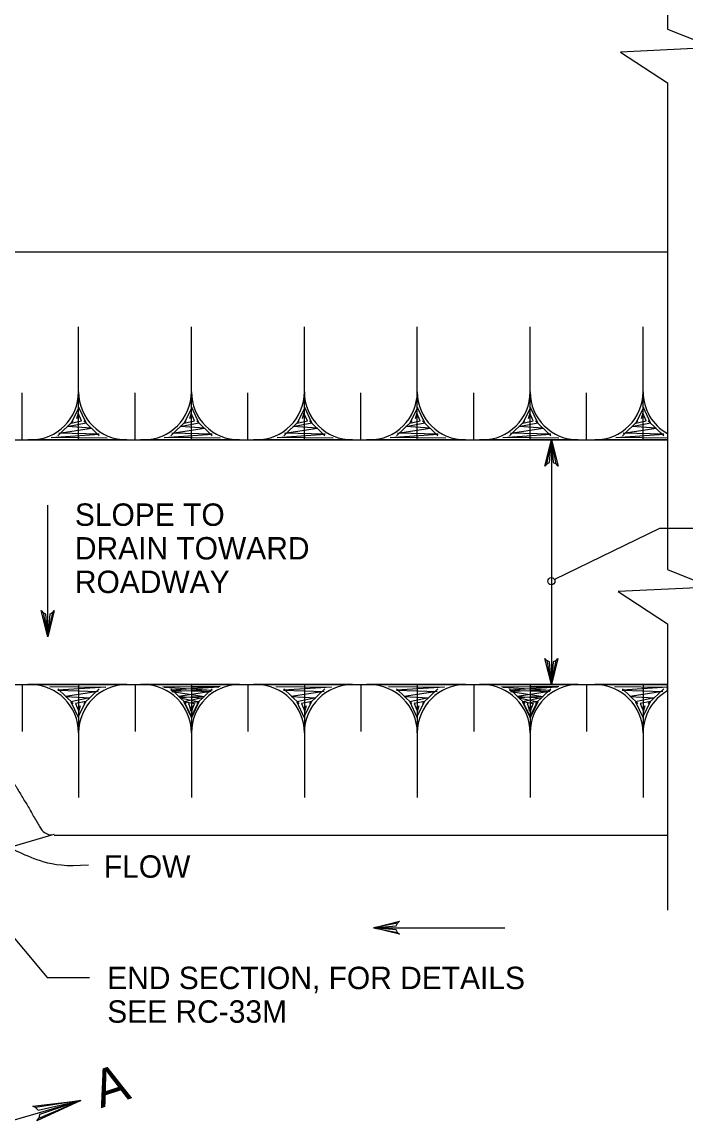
# Model space of a CAD drawing. Extents: x 636462 to 637367, y 299944 to 300538.
# Drawn here: x 636754.8 to 636843.6, y 300281.9 to 300429.2 of the extents above; entities that cross this region are included whole.
import ezdxf

# ---------------------------------------------------------------- set-up
doc = ezdxf.new("R2010")
doc.units = 0
doc.layers.add('Default', color=7, linetype='Continuous')

msp = doc.modelspace()

# ---------------------------------------------------------------- linework, layer by layer
at = {"layer": 'Default'}
for p, q in [((636841.16, 300465.99), (636841.16, 300428.23)), ((636841.16, 300421.06), (636841.16, 300355.93)), ((636726.65, 300398.45), (636841.16, 300398.45)), ((636762.35, 300373.27), (636762.35, 300388.38)), ((636777.45, 300373.27), (636777.45, 300388.38)), ((636792.56, 300373.27), (636792.56, 300388.38)), ((636807.67, 300373.27), (636807.67, 300388.38)), ((636822.78, 300373.27), (636822.78, 300388.38)), ((636837.89, 300373.27), (636837.89, 300388.38)), ((636754.79, 300373.27), (636754.79, 300379.56)), ((636769.9, 300373.27), (636769.9, 300379.56)), ((636785.01, 300373.27), (636785.01, 300379.56)), ((636800.12, 300373.27), (636800.12, 300379.56)), ((636815.23, 300373.27), (636815.23, 300379.56)), ((636830.33, 300373.27), (636830.33, 300379.56)), ((636759.59, 300373.83), (636761.64, 300375.82)), ((636765.1, 300373.83), (636763.05, 300375.82)), ((636765.1, 300373.83), (636763.05, 300375.82)), ((636765.1, 300373.83), (636763.05, 300375.82)), ((636774.7, 300373.83), (636776.75, 300375.82)), ((636780.21, 300373.83), (636778.16, 300375.82)), ((636780.21, 300373.83), (636778.16, 300375.82)), ((636780.21, 300373.83), (636778.16, 300375.82)), ((636789.81, 300373.83), (636791.86, 300375.82)), ((636795.32, 300373.83), (636793.27, 300375.82)), ((636795.32, 300373.83), (636793.27, 300375.82)), ((636795.32, 300373.83), (636793.27, 300375.82)), ((636804.91, 300373.83), (636806.97, 300375.82)), ((636810.43, 300373.83), (636808.38, 300375.82)), ((636810.43, 300373.83), (636808.38, 300375.82)), ((636810.43, 300373.83), (636808.38, 300375.82)), ((636820.02, 300373.83), (636822.07, 300375.82)), ((636825.54, 300373.83), (636823.49, 300375.82)), ((636825.54, 300373.83), (636823.49, 300375.82)), ((636825.54, 300373.83), (636823.49, 300375.82)), ((636835.13, 300373.83), (636837.18, 300375.82)), ((636840.65, 300373.83), (636838.59, 300375.82)), ((636733.01, 300373.27), (636841.16, 300373.27)), ((636768.79, 300373.27), (636755.54, 300373.27)), ((636755.54, 300373.27), (636755.9, 300373.27)), ((636783.89, 300373.27), (636770.65, 300373.27)), ((636770.65, 300373.27), (636771.01, 300373.27)), ((636799, 300373.27), (636785.76, 300373.27)), ((636785.76, 300373.27), (636786.12, 300373.27)), ((636814.11, 300373.27), (636800.87, 300373.27)), ((636800.87, 300373.27), (636801.23, 300373.27)), ((636810.61, 300373.27), (636822.17, 300373.27)), ((636829.22, 300373.27), (636815.98, 300373.27)), ((636815.98, 300373.27), (636816.34, 300373.27)), ((636825.62, 300373.27), (636825.62, 300340.53)), ((636841.16, 300373.27), (636831.45, 300373.27)), ((636841.16, 300374.1), (636841.16, 300373.27)), ((636825.62, 300353.05), (636825.62, 300342.78)), ((636841.16, 300348.66), (636841.16, 300310.33)), ((636725.91, 300340.53), (636841.16, 300340.53)), ((636754.79, 300340.53), (636754.79, 300334.24)), ((636768.79, 300340.53), (636755.54, 300340.53)), ((636755.54, 300340.53), (636755.9, 300340.53)), ((636759.59, 300339.97), (636761.64, 300337.98)), ((636762.35, 300340.53), (636762.35, 300325.42)), ((636765.1, 300339.97), (636763.05, 300337.98)), ((636769.9, 300340.53), (636769.9, 300334.24)), ((636783.89, 300340.53), (636770.65, 300340.53)), ((636770.65, 300340.53), (636771.01, 300340.53)), ((636774.7, 300339.97), (636776.75, 300337.98)), ((636777.45, 300340.53), (636777.45, 300325.42)), ((636780.21, 300339.97), (636778.16, 300337.98)), ((636780.21, 300339.97), (636778.16, 300337.98)), ((636780.21, 300339.97), (636778.16, 300337.98)), ((636780.21, 300339.97), (636778.16, 300337.98)), ((636785.01, 300340.53), (636785.01, 300334.24)), ((636799, 300340.53), (636785.76, 300340.53)), ((636785.76, 300340.53), (636786.12, 300340.53)), ((636789.8, 300339.97), (636791.86, 300337.98)), ((636792.56, 300340.53), (636792.56, 300325.42)), ((636795.32, 300339.97), (636793.27, 300337.98)), ((636800.12, 300340.53), (636800.12, 300334.24)), ((636814.11, 300340.53), (636800.87, 300340.53)), ((636800.87, 300340.53), (636801.23, 300340.53)), ((636804.91, 300339.97), (636806.96, 300337.98)), ((636807.67, 300340.53), (636807.67, 300325.42)), ((636810.43, 300339.97), (636808.38, 300337.98)), ((636815.23, 300340.53), (636815.23, 300334.24)), ((636829.22, 300340.53), (636815.98, 300340.53)), ((636815.98, 300340.53), (636816.34, 300340.53)), ((636818.17, 300340.53), (636822.17, 300340.53)), ((636820.02, 300339.97), (636822.07, 300337.98)), ((636822.78, 300340.53), (636822.78, 300325.42)), ((636825.54, 300339.97), (636823.48, 300337.98)), ((636825.54, 300339.97), (636823.49, 300337.98)), ((636825.54, 300339.97), (636823.49, 300337.98)), ((636825.54, 300339.97), (636823.49, 300337.98)), ((636830.33, 300340.53), (636830.33, 300334.24)), ((636841.16, 300340.53), (636831.45, 300340.53)), ((636835.13, 300339.97), (636837.18, 300337.98)), ((636835.13, 300339.97), (636837.18, 300337.98)), ((636837.89, 300340.53), (636837.89, 300325.42)), ((636840.65, 300339.97), (636838.59, 300337.98)), ((636841.16, 300339.7), (636841.16, 300340.53)), ((636726.5, 300310.97), (636759.06, 300320.5)), ((636759.06, 300320.39), (636841.16, 300320.39)), ((636752.38, 300281.88), (636762.67, 300284.89))]:
    msp.add_line(p, q, dxfattribs=at)
for points in [[(636841.16, 300428.23), (636847.38, 300425.75), (636834.88, 300425.14), (636841.16, 300421.06)], [(636766.18, 300373.51), (636758.7, 300373.61), (636765.12, 300374.02), (636759.7, 300374.18), (636764.09, 300374.86), (636760.82, 300375.05), (636763.36, 300375.56), (636762.39, 300377.62), (636761.37, 300375.53), (636762.75, 300375.82), (636762.3, 300376.85), (636762.07, 300376.08)], [(636766.18, 300373.51), (636758.7, 300373.61), (636765.12, 300374.02), (636759.7, 300374.18), (636764.09, 300374.86), (636760.82, 300375.05), (636763.36, 300375.56), (636762.39, 300377.62), (636761.37, 300375.53), (636762.75, 300375.82), (636762.3, 300376.85), (636762.07, 300376.08)], [(636781.29, 300373.51), (636773.81, 300373.61), (636780.23, 300374.02), (636774.81, 300374.18), (636779.2, 300374.86), (636775.93, 300375.05), (636778.46, 300375.56), (636777.5, 300377.62), (636776.47, 300375.53), (636777.85, 300375.82), (636777.41, 300376.85), (636777.18, 300376.08)], [(636781.29, 300373.51), (636773.81, 300373.61), (636780.23, 300374.02), (636774.81, 300374.18), (636779.2, 300374.86), (636775.93, 300375.05), (636778.46, 300375.56), (636777.5, 300377.62), (636776.47, 300375.53), (636777.85, 300375.82), (636777.41, 300376.85), (636777.18, 300376.08)], [(636796.4, 300373.51), (636788.92, 300373.61), (636795.34, 300374.02), (636789.92, 300374.18), (636794.31, 300374.86), (636791.04, 300375.05), (636793.57, 300375.56), (636792.61, 300377.62), (636791.58, 300375.53), (636792.96, 300375.82), (636792.51, 300376.85), (636792.29, 300376.08)], [(636796.4, 300373.51), (636788.92, 300373.61), (636795.34, 300374.02), (636789.92, 300374.18), (636794.31, 300374.86), (636791.04, 300375.05), (636793.57, 300375.56), (636792.61, 300377.62), (636791.58, 300375.53), (636792.96, 300375.82), (636792.51, 300376.85), (636792.29, 300376.08)], [(636811.5, 300373.51), (636804.03, 300373.61), (636810.45, 300374.02), (636805.02, 300374.18), (636809.42, 300374.86), (636806.15, 300375.05), (636808.68, 300375.56), (636807.72, 300377.62), (636806.69, 300375.53), (636808.07, 300375.82), (636807.62, 300376.85), (636807.4, 300376.08)], [(636811.5, 300373.51), (636804.03, 300373.61), (636810.45, 300374.02), (636805.02, 300374.18), (636809.42, 300374.86), (636806.15, 300375.05), (636808.68, 300375.56), (636807.72, 300377.62), (636806.69, 300375.53), (636808.07, 300375.82), (636807.62, 300376.85), (636807.4, 300376.08)], [(636826.61, 300373.51), (636819.14, 300373.61), (636825.55, 300374.02), (636820.13, 300374.18), (636824.53, 300374.86), (636821.26, 300375.05), (636823.79, 300375.56), (636822.83, 300377.62), (636821.8, 300375.53), (636823.18, 300375.82), (636822.73, 300376.85), (636822.51, 300376.08)], [(636826.61, 300373.51), (636819.14, 300373.61), (636825.55, 300374.02), (636820.13, 300374.18), (636824.53, 300374.86), (636821.26, 300375.05), (636823.79, 300375.56), (636822.83, 300377.62), (636821.8, 300375.53), (636823.18, 300375.82), (636822.73, 300376.85), (636822.51, 300376.08)], [(636841.16, 300373.52), (636834.25, 300373.61), (636840.66, 300374.02), (636835.24, 300374.18), (636839.64, 300374.86), (636836.37, 300375.05), (636838.9, 300375.56), (636837.94, 300377.62), (636836.91, 300375.53), (636838.29, 300375.82), (636837.84, 300376.85), (636837.62, 300376.08)], [(636824.98, 300370.03), (636824.76, 300369.77), (636825.62, 300373.27), (636824.98, 300370.03), (636825.36, 300370.23), (636825.62, 300373.27), (636825.88, 300370.24), (636826.25, 300370.06), (636825.62, 300373.27), (636826.51, 300369.77), (636826.25, 300370.06)], [(636758.24, 300346.94), (636758.24, 300358.86), (636758.24, 300364.53)], [(636848.61, 300361.41), (636842.08, 300361.41), (636840.07, 300361.41), (636826.05, 300354.57)], [(636841.16, 300355.93), (636847.03, 300353.58), (636834.54, 300352.97), (636841.16, 300348.66)], [(636758.88, 300350.17), (636759.1, 300350.44), (636758.24, 300346.94), (636758.88, 300350.17), (636758.5, 300349.97), (636758.24, 300346.94), (636757.98, 300349.97), (636757.6, 300350.15), (636758.24, 300346.94), (636757.35, 300350.43), (636757.6, 300350.15)], [(636826.26, 300343.76), (636826.48, 300344.03), (636825.62, 300340.53), (636826.26, 300343.76), (636825.88, 300343.57), (636825.62, 300340.53), (636825.36, 300343.56), (636824.99, 300343.74), (636825.62, 300340.53), (636824.73, 300344.03), (636824.99, 300343.74)], [(636758.51, 300340.29), (636765.99, 300340.19), (636759.57, 300339.78), (636764.99, 300339.61), (636760.6, 300338.94), (636763.87, 300338.75), (636761.33, 300338.24), (636762.3, 300336.18), (636763.32, 300338.27), (636761.94, 300337.98), (636762.39, 300336.95), (636762.62, 300337.72)], [(636773.62, 300340.29), (636781.1, 300340.19), (636774.68, 300339.78), (636780.1, 300339.61), (636775.71, 300338.94), (636778.98, 300338.75), (636776.44, 300338.24), (636777.41, 300336.18), (636778.43, 300338.27), (636777.05, 300337.98), (636777.5, 300336.95), (636777.73, 300337.72)], [(636781.29, 300340.29), (636773.81, 300340.19), (636780.23, 300339.78), (636774.81, 300339.61), (636779.2, 300338.94), (636775.93, 300338.75), (636778.46, 300338.24), (636777.5, 300336.18), (636776.47, 300338.27), (636777.85, 300337.98), (636777.41, 300336.95), (636777.18, 300337.72)], [(636781.29, 300340.29), (636773.81, 300340.19), (636780.23, 300339.78), (636774.81, 300339.61), (636779.2, 300338.94), (636775.93, 300338.75), (636778.46, 300338.24), (636777.5, 300336.18), (636776.47, 300338.27), (636777.85, 300337.98), (636777.41, 300336.95), (636777.18, 300337.72)], [(636788.73, 300340.29), (636796.2, 300340.19), (636789.79, 300339.78), (636795.21, 300339.61), (636790.81, 300338.94), (636794.09, 300338.75), (636791.55, 300338.24), (636792.51, 300336.18), (636793.54, 300338.27), (636792.16, 300337.98), (636792.61, 300336.95), (636792.83, 300337.72)], [(636803.84, 300340.29), (636811.31, 300340.19), (636804.9, 300339.78), (636810.32, 300339.61), (636805.92, 300338.94), (636809.19, 300338.75), (636806.66, 300338.24), (636807.62, 300336.18), (636808.65, 300338.27), (636807.27, 300337.98), (636807.72, 300336.95), (636807.94, 300337.72)], [(636818.95, 300340.29), (636826.42, 300340.19), (636820.01, 300339.78), (636825.43, 300339.61), (636821.03, 300338.94), (636824.3, 300338.75), (636821.77, 300338.24), (636822.73, 300336.18), (636823.76, 300338.27), (636822.38, 300337.98), (636822.83, 300336.95), (636823.05, 300337.72)], [(636826.61, 300340.29), (636819.14, 300340.19), (636825.55, 300339.78), (636820.13, 300339.61), (636824.53, 300338.94), (636821.26, 300338.75), (636823.79, 300338.24), (636822.83, 300336.18), (636821.8, 300338.27), (636823.18, 300337.98), (636822.73, 300336.95), (636822.51, 300337.72)], [(636826.61, 300340.29), (636819.14, 300340.19), (636825.55, 300339.78), (636820.13, 300339.61), (636824.53, 300338.94), (636821.26, 300338.75), (636823.79, 300338.24), (636822.83, 300336.18), (636821.8, 300338.27), (636823.18, 300337.98), (636822.73, 300336.95), (636822.51, 300337.72)], [(636834.05, 300340.29), (636841.16, 300340.2)], [(636841.16, 300340.17), (636835.11, 300339.78), (636840.53, 300339.61), (636836.14, 300338.94), (636839.41, 300338.75), (636836.88, 300338.24), (636837.84, 300336.18), (636838.87, 300338.27), (636837.49, 300337.98), (636837.94, 300336.95), (636838.16, 300337.72)], [(636745.45, 300316.52), (636758.15, 300301.36), (636763.81, 300301.36)], [(636805.03, 300307.36), (636805.3, 300307.14), (636801.8, 300308), (636805.03, 300307.36), (636804.83, 300307.73), (636801.8, 300308), (636804.83, 300308.26), (636805.01, 300308.63), (636801.8, 300308), (636805.29, 300308.88), (636805.01, 300308.63)], [(636801.8, 300308), (636813.71, 300308), (636819.38, 300308)], [(636756.59, 300283.95), (636756.93, 300283.59), (636762.67, 300284.89), (636756.59, 300283.95), (636756.22, 300284.12), (636762.67, 300284.89), (636757.11, 300283), (636757.02, 300282.52), (636762.67, 300284.89), (636756.78, 300282.15), (636757.02, 300282.52)]]:
    msp.add_lwpolyline(points, dxfattribs=at)
msp.add_circle((636825.62, 300354.36), 0.481, dxfattribs=at)
for centre, start, end in [((636755.9, 300379.71), 270, 0), ((636755.9, 300379.71), 270, 0), ((636768.79, 300379.71), 180, 270), ((636768.79, 300379.71), 180, 270), ((636768.79, 300379.71), 180, 270), ((636768.79, 300379.71), 180, 270), ((636771.01, 300379.71), 270, 0), ((636771.01, 300379.71), 270, 0), ((636783.89, 300379.71), 180, 270), ((636783.89, 300379.71), 180, 270), ((636783.89, 300379.71), 180, 270), ((636783.89, 300379.71), 180, 270), ((636786.12, 300379.71), 270, 0), ((636786.12, 300379.71), 270, 0), ((636799, 300379.71), 180, 270), ((636799, 300379.71), 180, 270), ((636799, 300379.71), 180, 270), ((636799, 300379.71), 180, 270), ((636801.23, 300379.71), 270, 0), ((636801.23, 300379.71), 270, 0), ((636814.11, 300379.71), 180, 270), ((636814.11, 300379.71), 180, 270), ((636814.11, 300379.71), 180, 270), ((636814.11, 300379.71), 180, 270), ((636816.34, 300379.71), 270, 0), ((636816.34, 300379.71), 270, 0), ((636829.22, 300379.71), 180, 270), ((636829.22, 300379.71), 180, 270), ((636829.22, 300379.71), 180, 270), ((636829.22, 300379.71), 180, 270), ((636831.45, 300379.71), 270, 0), ((636831.45, 300379.71), 270, 0), ((636844.33, 300379.71), 180, 240.5216), ((636844.33, 300379.71), 180, 240.5216), ((636755.9, 300334.09), 0, 90), ((636755.9, 300334.09), 0, 90), ((636768.79, 300334.09), 90, 180), ((636768.79, 300334.09), 90, 180), ((636768.79, 300334.09), 90, 180), ((636768.79, 300334.09), 90, 180), ((636768.79, 300334.09), 90, 180), ((636771.01, 300334.09), 0, 90), ((636771.01, 300334.09), 0, 90), ((636783.89, 300334.09), 90, 180), ((636783.89, 300334.09), 90, 180), ((636783.89, 300334.09), 90, 180), ((636783.89, 300334.09), 90, 180), ((636783.89, 300334.09), 90, 180), ((636786.12, 300334.09), 0, 90), ((636786.12, 300334.09), 0, 90), ((636799, 300334.09), 90, 180), ((636799, 300334.09), 90, 180), ((636799, 300334.09), 90, 180), ((636799, 300334.09), 90, 180), ((636799, 300334.09), 90, 180), ((636801.23, 300334.09), 0, 90), ((636801.23, 300334.09), 0, 90), ((636814.11, 300334.09), 90, 180), ((636814.11, 300334.09), 90, 180), ((636814.11, 300334.09), 90, 180), ((636814.11, 300334.09), 90, 180), ((636814.11, 300334.09), 90, 180), ((636816.34, 300334.09), 0, 90), ((636816.34, 300334.09), 0, 90), ((636829.22, 300334.09), 90, 180), ((636829.22, 300334.09), 90, 180), ((636829.22, 300334.09), 90, 180), ((636829.22, 300334.09), 90, 180), ((636829.22, 300334.09), 90, 180), ((636831.45, 300334.09), 0, 90), ((636831.45, 300334.09), 0, 90), ((636831.45, 300334.09), 0, 90), ((636844.33, 300334.09), 119.4776, 180), ((636844.33, 300334.09), 119.4784, 180)]:
    msp.add_arc(centre, 6.44, start, end, dxfattribs=at)
for points in [[(636741.64, 300339.35), (636742.92, 300338.86), (636744.06, 300338.26), (636745.19, 300337.5), (636746.41, 300336.69), (636747.55, 300335.86), (636748.51, 300334.77), (636749.97, 300333.1), (636751.29, 300331.37), (636752.42, 300329.49), (636753.2, 300328.19), (636753.98, 300326.89), (636754.76, 300325.58), (636755.62, 300324.16), (636756.43, 300322.72), (636757.3, 300321.28), (636757.64, 300320.73), (636758.52, 300320.36), (636759.06, 300320.5)], [(636763.67, 300316.37), (636760.62, 300316.14), (636757.45, 300316.7), (636754.43, 300318.07), (636751.71, 300319.3), (636749.48, 300320.72), (636747.37, 300322.69)]]:
    msp.add_open_spline(points, degree=3, dxfattribs=at)

# ---------------------------------------------------------------- texts
for s, p in [('SLOPE TO', (636761.85, 300361.77)), ('DRAIN TOWARD', (636761.85, 300357.27)), ('ROADWAY', (636761.85, 300352.78)), ('FLOW', (636765.73, 300314.69)), ('END SECTION, FOR DETAILS', (636766.18, 300299.79)), ('SEE RC-33M', (636766.18, 300295.29))]:
    msp.add_text(s, height=2.998, dxfattribs=at).set_placement(p)
msp.add_text('A', height=5, rotation=18.0505, dxfattribs=at).set_placement((636765.31, 300283.83))

doc.saveas('drawing.dxf')
